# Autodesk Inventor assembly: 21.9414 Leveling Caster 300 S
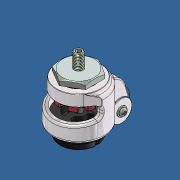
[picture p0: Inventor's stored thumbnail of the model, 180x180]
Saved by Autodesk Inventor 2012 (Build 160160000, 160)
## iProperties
Created: 2015-01
Part Number: 21.9414 Leveling Caster 300 S
Document SubType Name: Assembly
Designer: Admin
Author: Admin
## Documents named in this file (6)
- C:\Andys Backup Data\ANDY'S INVENTOR\INVENTOR LIBRARIES\PARTS LIBRARY\FEET WHEELS FLOOR FASTENING SUPPORTS\21.9414 Leveling Caster 300 S.iam
- C:\Andys Backup Data\ANDY'S INVENTOR\INVENTOR LIBRARIES\PARTS LIBRARY\FEET WHEELS FLOOR FASTENING SUPPORTS\SUBCOMPONENTS\21.9414 Leveling Caster 300 S Body.ipt
- C:\Andys Backup Data\ANDY'S INVENTOR\INVENTOR LIBRARIES\PARTS LIBRARY\FEET WHEELS FLOOR FASTENING SUPPORTS\SUBCOMPONENTS\21.9414 Leveling Caster 300 S Wheel.ipt
- C:\Andys Backup Data\ANDY'S INVENTOR\INVENTOR LIBRARIES\PARTS LIBRARY\FASTENING ELEMENTS\SET SCREWS\SET SCREW M12X35 FLAT END.ipt
- C:\Andys Backup Data\ANDY'S INVENTOR\INVENTOR LIBRARIES\PARTS LIBRARY\FASTENING ELEMENTS\NUTS\21.1528 M12 HEX NUT.ipt
- C:\Andys Backup Data\ANDY'S INVENTOR\INVENTOR LIBRARIES\PARTS LIBRARY\FASTENING ELEMENTS\NUTS\21.1527 M10 HEX NUT.ipt
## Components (5 placed, 5 different names)
1. 21.9414 Leveling Caster 300 S Body:1 — Mate:1, Mate:2, Mate:3, Flush:1, Insert:1, Insert:2
2. 21.9414 Leveling Caster 300 S Wheel:1 — Mate:1, Mate:2
3. SET SCREW M12X35 FLAT END:1 — Mate:3, Flush:1
4. 21.1528 M12 HEX NUT:1 — Insert:1
5. 21.1527 M10 HEX NUT:1 — Insert:2
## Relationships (6: Mate 3, Insert 2, Flush 1)
- Mate:1: 21.9414 Leveling Caster 300 S Body:1 ↔ 21.9414 Leveling Caster 300 S Wheel:1
- Mate:2: 21.9414 Leveling Caster 300 S Body:1 ↔ 21.9414 Leveling Caster 300 S Wheel:1
- Mate:3: 21.9414 Leveling Caster 300 S Body:1 ↔ SET SCREW M12X35 FLAT END:1
- Flush:1: 21.9414 Leveling Caster 300 S Body:1 ↔ SET SCREW M12X35 FLAT END:1
- Insert:1: 21.9414 Leveling Caster 300 S Body:1 ↔ 21.1528 M12 HEX NUT:1
- Insert:2: 21.9414 Leveling Caster 300 S Body:1 ↔ 21.1527 M10 HEX NUT:1
